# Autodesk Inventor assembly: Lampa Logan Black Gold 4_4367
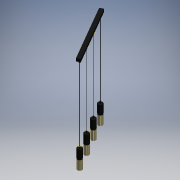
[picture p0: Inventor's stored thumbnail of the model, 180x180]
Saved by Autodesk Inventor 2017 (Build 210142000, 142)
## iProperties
Created: 2020-09
Part Number: Lampa Logan Black Gold 4_4367
Document SubType Name: Assembly
Designer: Admin
Author: Admin
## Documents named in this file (4)
- D:\TK Lighting\Projekty Lamp\Lampa Logan Black Gold 4_4367.iam
- D:\TK Lighting\NOwe\Logan Black\Zawiesie_4.ipt
- D:\TK Lighting\NOwe\Logan Black\Lampa Logan Black Gold do 4.ipt
- D:\TK Lighting\NOwe\Logan Black\Lampa Logan Black Gold bez zawiesia.iam
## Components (9 placed, 3 different names)
1. Zawiesie_4:1 — Mate:1, Mate:2, Mate:3, Mate:4, Mate:5, Mate:6, Mate:7, Mate:8
2. Lampa Logan Black Gold do 4:1 — Mate:1, Mate:2, Mate:9, Mate:13
3. Lampa Logan Black Gold do 4:2 — Mate:3, Mate:4, Mate:10, Mate:14
4. Lampa Logan Black Gold do 4:3 — Mate:7, Mate:8, Mate:12, Mate:16
5. Lampa Logan Black Gold do 4:4 — Mate:5, Mate:6, Mate:11, Mate:15
6. Lampa Logan Black Gold bez zawiesia:1 [sub-assembly] — Mate:9, Mate:13
7. Lampa Logan Black Gold bez zawiesia:2 [sub-assembly] — Mate:10, Mate:14
8. Lampa Logan Black Gold bez zawiesia:3 [sub-assembly] — Mate:11, Mate:15
9. Lampa Logan Black Gold bez zawiesia:4 [sub-assembly] — Mate:12, Mate:16
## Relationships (16: Mate 16)
- Mate:1: Zawiesie_4:1 ↔ Lampa Logan Black Gold do 4:1
- Mate:2: Zawiesie_4:1 ↔ Lampa Logan Black Gold do 4:1
- Mate:3: Zawiesie_4:1 ↔ Lampa Logan Black Gold do 4:2
- Mate:4: Zawiesie_4:1 ↔ Lampa Logan Black Gold do 4:2
- Mate:5: Zawiesie_4:1 ↔ Lampa Logan Black Gold do 4:4
- Mate:6: Zawiesie_4:1 ↔ Lampa Logan Black Gold do 4:4
- Mate:7: Zawiesie_4:1 ↔ Lampa Logan Black Gold do 4:3
- Mate:8: Zawiesie_4:1 ↔ Lampa Logan Black Gold do 4:3
- Mate:9: Lampa Logan Black Gold do 4:1 ↔ Lampa Logan Black Gold bez zawiesia:1
- Mate:10: Lampa Logan Black Gold do 4:2 ↔ Lampa Logan Black Gold bez zawiesia:2
- Mate:11: Lampa Logan Black Gold do 4:4 ↔ Lampa Logan Black Gold bez zawiesia:3
- Mate:12: Lampa Logan Black Gold do 4:3 ↔ Lampa Logan Black Gold bez zawiesia:4
- Mate:13: Lampa Logan Black Gold do 4:1 ↔ Lampa Logan Black Gold bez zawiesia:1
- Mate:14: Lampa Logan Black Gold do 4:2 ↔ Lampa Logan Black Gold bez zawiesia:2
- Mate:15: Lampa Logan Black Gold do 4:4 ↔ Lampa Logan Black Gold bez zawiesia:3
- Mate:16: Lampa Logan Black Gold do 4:3 ↔ Lampa Logan Black Gold bez zawiesia:4
